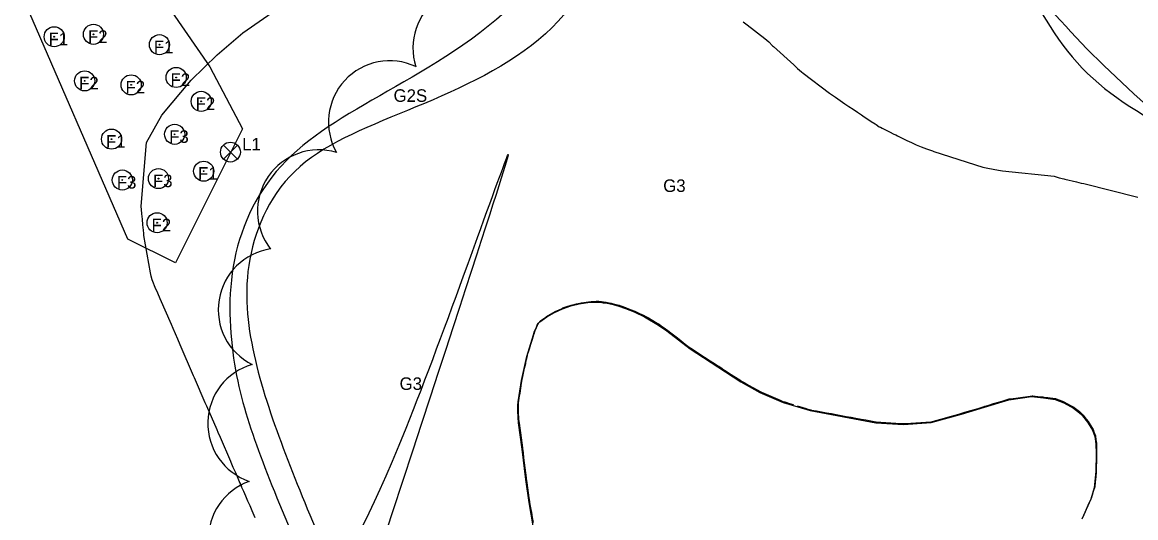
# Model space of a CAD drawing. Extents: x 0 to 512122, y 0 to 6212554.
# Drawn here: x 511390.7 to 511501.5, y 6211379.6 to 6211428.9 of the extents above; entities that cross this region are included whole.
import ezdxf

# ---------------------------------------------------------------- set-up
doc = ezdxf.new("R2010")
doc.units = 0
for name, color, linetype in [('_Låge L1', 7, 'Continuous'), ('_ny fruit trees', 7, 'Continuous'), ('_Paths', 7, 'Continuous'), ('_Spredmingskorridor', 7, 'Continuous'), ('_Spredmingskorridor_hatch', 7, 'Continuous'), ('Bassin - bottom', 7, 'Continuous'), ('Clouds', 7, 'Continuous'), ('MatrikelnummerMaster', 7, 'Continuous'), ('TV_U_AFM_Symbl_Gul', 7, 'Continuous'), ('TV_U_LYS_Nyx330-Trafiksti-x2', 7, 'Continuous')]:
    doc.layers.add(name, color=color, linetype=linetype)

msp = doc.modelspace()

# ---------------------------------------------------------------- linework, layer by layer
at = {"layer": '_Låge L1'}
for p, q in [((511412.11, 6211416.7), (511410.71, 6211415.3)), ((511410.71, 6211416.7), (511412.11, 6211415.3))]:
    msp.add_line(p, q, dxfattribs=at)
msp.add_circle((511411.41, 6211416), 0.989, dxfattribs=at)
at = {"layer": '_ny fruit trees'}
for centre, radius in [((511393.87, 6211427.48), 1), ((511397.78, 6211427.72), 1), ((511393.87, 6211427.48), 0.0426), ((511397.78, 6211427.72), 0.0426), ((511404.34, 6211426.69), 1), ((511404.34, 6211426.69), 0.0426), ((511396.9, 6211423.09), 1), ((511401.53, 6211422.69), 1), ((511406.01, 6211423.43), 1), ((511396.9, 6211423.09), 0.0426), ((511401.53, 6211422.69), 0.0426), ((511406.01, 6211423.43), 0.0426), ((511408.5, 6211421.05), 1), ((511408.5, 6211421.05), 0.0426), ((511399.58, 6211417.29), 1), ((511405.86, 6211417.77), 1), ((511399.58, 6211417.29), 0.0426), ((511405.86, 6211417.77), 0.0426), ((511408.75, 6211414.1), 1), ((511400.65, 6211413.22), 1), ((511404.25, 6211413.36), 1), ((511408.75, 6211414.1), 0.0426), ((511400.65, 6211413.22), 0.0426), ((511404.25, 6211413.36), 0.0426), ((511404.11, 6211408.97), 1), ((511404.11, 6211408.97), 0.0426)]:
    msp.add_circle(centre, radius, dxfattribs=at)
at = {"layer": '_Paths'}
for points in [[(511619.19, 6211386.8), (511596.58, 6211393.48), (511585.39, 6211391.46), (511574.07, 6211393.08), (511564.35, 6211396.52), (511555.15, 6211400.37), (511543.4, 6211408.32), (511538, 6211417.07), (511534.53, 6211422.71), (511527.54, 6211428.6), (511520.9, 6211430.59), (511516.51, 6211433.06), (511513.01, 6211439.69), (511510.47, 6211444.11), (511507.78, 6211450.66), (511503.38, 6211454.99), (511500.2, 6211458.08), (511497.38, 6211464.57)], [(511614.91, 6211385.47), (511596.46, 6211390.92), (511585.44, 6211388.93), (511573.47, 6211390.64), (511563.45, 6211394.19), (511553.96, 6211398.16), (511541.55, 6211406.55), (511535.88, 6211415.76), (511532.61, 6211421.05), (511526.33, 6211426.35), (511519.92, 6211428.28), (511514.64, 6211431.24), (511510.82, 6211438.49), (511508.22, 6211443.01), (511505.66, 6211449.24), (511501.63, 6211453.21), (511498.11, 6211456.63), (511495.08, 6211463.57)], [(511450.04, 6211448.86), (511448.66, 6211442.81), (511441.76, 6211430.61), (511427.39, 6211422.18), (511415.87, 6211415.8), (511410.87, 6211405.41), (511411.54, 6211394.31), (511413.91, 6211386.76), (511418.06, 6211376.54), (511422.94, 6211366.11), (511450.04, 6211448.86), (511422.94, 6211366.11)], [(511452.49, 6211448.38), (511452.1, 6211446.36), (511450.74, 6211439.4), (511444.07, 6211426.76), (511429.55, 6211420.18), (511417.02, 6211415.5), (511412.4, 6211405.18), (511413.42, 6211395.79), (511416.52, 6211386.63), (511420.5, 6211376.91), (511423.94, 6211369.77), (511425.26, 6211367.04)]]:
    msp.add_open_spline(points, degree=3, dxfattribs=at)
at = {"layer": '_Spredmingskorridor'}
for points in [[(511618.63, 6211420.62), (511606.03, 6211410.57), (511596.93, 6211398.18), (511583.32, 6211390.02), (511570.81, 6211390.17), (511555.01, 6211396.48), (511539.8, 6211408.82), (511527.66, 6211423.86), (511513.19, 6211431.42), (511508.4, 6211440.66), (511501.75, 6211451.71), (511492.27, 6211459.06), (511618.63, 6211420.62), (511492.27, 6211459.06)], [(511446.92, 6211452.59), (511459.02, 6211449.61), (511483.05, 6211444.24), (511494.74, 6211426.25), (511518, 6211408.46), (511535.13, 6211387.3), (511545.81, 6211384.87), (511574.75, 6211382.07), (511593.15, 6211386.6), (511609.3, 6211398.19), (511446.92, 6211452.59), (511609.3, 6211398.19)]]:
    msp.add_open_spline(points, degree=3, dxfattribs=at)
at = {"layer": '_Spredmingskorridor_hatch'}
for points in [[(511581.75, 6211389.91), (511577.7, 6211389.37), (511567.86, 6211390.32), (511554, 6211396.47), (511538.61, 6211407.6), (511530.73, 6211425.91), (511512.75, 6211428.39), (511508.4, 6211441.83), (511502.76, 6211452.31), (511495.71, 6211456.96), (511492.31, 6211459.2)], [(511467.29, 6211448.87), (511473.27, 6211448.33), (511486.52, 6211446.7), (511493.23, 6211420.77), (511520.95, 6211413.24), (511528.73, 6211386.92), (511552.28, 6211384.43), (511571.21, 6211380.37), (511589.49, 6211384.41), (511596.58, 6211388.53), (511598.18, 6211389.58)]]:
    msp.add_open_spline(points, degree=3, dxfattribs=at)
at = {"layer": 'Bassin - bottom'}
msp.add_lwpolyline([(511441.56, 6211378.81), (511441.16, 6211381.14), (511440.83, 6211383.42), (511440.46, 6211386.44), (511440.1, 6211389.06), (511440.03, 6211390.23), (511440.03, 6211390.8), (511440.06, 6211391.15), (511440.39, 6211393.28), (511440.92, 6211395.67), (511441.58, 6211397.82), (511441.69, 6211398.18), (511441.83, 6211398.47), (511441.96, 6211398.76), (511442.06, 6211398.93), (511442.11, 6211399), (511442.15, 6211399.05), (511442.2, 6211399.1), (511442.91, 6211399.61), (511443.67, 6211400.05), (511444.46, 6211400.41), (511445.29, 6211400.7), (511446.13, 6211400.91), (511447, 6211401.03), (511447.87, 6211401.08), (511448.03, 6211401.07), (511448.2, 6211401.05), (511448.5, 6211401.01), (511448.9, 6211400.95), (511449.37, 6211400.85), (511450.07, 6211400.68), (511450.75, 6211400.42), (511451.6, 6211400.09), (511452.63, 6211399.6), (511454.03, 6211398.79), (511454.85, 6211398.2), (511457.19, 6211396.41), (511459.94, 6211394.62), (511462.23, 6211393.14), (511464.1, 6211392.09), (511466.42, 6211391.09), (511469.12, 6211390.27), (511475.64, 6211389.07), (511478.42, 6211388.9), (511481.15, 6211389.1), (511484.18, 6211389.93), (511486.47, 6211390.63), (511488.88, 6211391.36), (511491.16, 6211391.66), (511492.33, 6211391.55), (511493.49, 6211391.39), (511494.38, 6211391.04), (511495.32, 6211390.52), (511496.09, 6211389.92), (511496.73, 6211389.11), (511497.23, 6211388.32), (511497.47, 6211387.69), (511497.57, 6211386.98), (511497.58, 6211385.96), (511497.54, 6211384.21), (511497.4, 6211382.59), (511497.04, 6211381.47), (511496.15, 6211379.46)], dxfattribs=at)
at = {"layer": 'Clouds'}
for centre, start, end in [((511435.68, 6211426.38), 52.9408, 197.9408), ((511427.27, 6211418.99), 64.7309, 209.7309), ((511420.21, 6211410.12), 73.1767, 218.1767), ((511416.3, 6211400.32), 98.3357, 243.3357), ((511415.26, 6211389), 106.1484, 251.1484), ((511415.32, 6211377.48), 109.4778, 254.4778)]:
    msp.add_arc(centre, 6.1, start, end, dxfattribs=at)
at = {"layer": 'MatrikelnummerMaster'}
msp.add_lwpolyline([(511390.69, 6211431.59), (511399.26, 6211439.11), (511409.35, 6211424.49), (511412.6, 6211418.32), (511405.93, 6211404.98), (511401.2, 6211407.34), (511390.69, 6211431.59), (511390.69, 6211431.59), (511390.69, 6211431.59), (511390.69, 6211431.59), (511390.69, 6211431.59)], dxfattribs=at)
at = {"layer": 'TV_U_LYS_Nyx330-Trafiksti-x2'}
for points in [[(511413.88, 6211379.6), (511413.57, 6211380.31), (511413.36, 6211380.79), (511413.16, 6211381.26), (511412.95, 6211381.74), (511412.74, 6211382.22), (511412.53, 6211382.7), (511412.35, 6211383.13), (511412.53, 6211382.71), (511412.32, 6211383.19), (511412.12, 6211383.67), (511411.91, 6211384.14), (511411.7, 6211384.62), (511411.5, 6211385.1), (511411.45, 6211385.19), (511410.41, 6211387.61), (511410.2, 6211388.09), (511410.08, 6211388.36), (511409.06, 6211390.72), (511408.91, 6211391.06), (511407.83, 6211393.54), (511407.75, 6211393.74), (511406.41, 6211396.82), (511406.17, 6211397.37), (511405.94, 6211397.91), (511405.7, 6211398.45), (511405.54, 6211398.83), (511404.42, 6211401.41), (511404.18, 6211401.97), (511403.93, 6211402.54), (511403.69, 6211403.11), (511403.61, 6211403.28), (511403.52, 6211403.65), (511403.45, 6211403.97), (511402.79, 6211407.7), (511402.78, 6211407.89), (511402.75, 6211408.24), (511402.7, 6211408.77), (511402.65, 6211409.31), (511402.6, 6211409.85), (511402.6, 6211409.9), (511402.53, 6211410.63), (511403.06, 6211416.95), (511404.59, 6211419.67), (511407.5, 6211423.15), (511410.09, 6211425.68), (511412.65, 6211427.86), (511418.83, 6211432.18)], [(511462.45, 6211428.96), (511462.84, 6211428.68), (511464.61, 6211427.32), (511465, 6211426.96), (511465.37, 6211426.59), (511465.46, 6211426.51), (511467.49, 6211424.67), (511467.87, 6211424.33), (511468.25, 6211423.99), (511468.43, 6211423.84), (511471.03, 6211421.87), (511471.44, 6211421.59), (511471.64, 6211421.45), (511472.57, 6211420.81), (511472.98, 6211420.54), (511473.4, 6211420.26), (511473.82, 6211419.98), (511474.23, 6211419.7), (511474.5, 6211419.52), (511474.77, 6211419.34), (511475.19, 6211419.06), (511475.58, 6211418.8), (511475.68, 6211418.73), (511475.99, 6211418.53), (511476.11, 6211418.47), (511476.27, 6211418.39), (511476.56, 6211418.25), (511477.01, 6211418.02), (511477.46, 6211417.8), (511477.64, 6211417.71), (511477.82, 6211417.63), (511478.29, 6211417.4), (511478.75, 6211417.17), (511479.22, 6211416.94), (511479.68, 6211416.71), (511480.16, 6211416.51), (511480.7, 6211416.32), (511481.29, 6211416.11), (511481.43, 6211416.05), (511486.3, 6211414.51), (511486.82, 6211414.4), (511487.34, 6211414.29), (511487.86, 6211414.2), (511488.28, 6211414.15), (511493.4, 6211413.6), (511493.89, 6211413.45), (511494.38, 6211413.33), (511494.47, 6211413.31), (511495.62, 6211413.03), (511496.11, 6211412.92), (511496.37, 6211412.86), (511501.73, 6211411.53)], [(511441.57, 6211379.14), (511441.48, 6211379.63), (511441.4, 6211380.12), (511441.31, 6211380.61), (511441.23, 6211381.11), (511441.21, 6211381.21), (511441.15, 6211381.6), (511441.08, 6211382.1), (511441.01, 6211382.59), (511440.94, 6211383.09), (511440.88, 6211383.5), (511440.87, 6211383.58), (511440.81, 6211384.08), (511440.75, 6211384.57), (511440.69, 6211385.07), (511440.63, 6211385.57), (511440.57, 6211386.06), (511440.52, 6211386.51), (511440.51, 6211386.56), (511440.44, 6211387.05), (511440.37, 6211387.55), (511440.31, 6211388.05), (511440.24, 6211388.54), (511440.17, 6211389.04), (511440.16, 6211389.13), (511440.13, 6211389.53), (511440.1, 6211390.03), (511440.08, 6211390.3), (511440.08, 6211390.53), (511440.08, 6211390.88), (511440.1, 6211391.03), (511440.11, 6211391.23), (511440.16, 6211391.53), (511440.24, 6211392.02), (511440.31, 6211392.52), (511440.39, 6211393.01), (511440.44, 6211393.36), (511440.48, 6211393.5), (511440.58, 6211393.99), (511440.69, 6211394.48), (511440.8, 6211394.97), (511440.83, 6211395.12), (511440.9, 6211395.46), (511440.97, 6211395.74), (511441.03, 6211395.94), (511441.08, 6211396.11), (511441.18, 6211396.42), (511441.32, 6211396.9), (511441.47, 6211397.37), (511441.62, 6211397.85), (511441.63, 6211397.9), (511441.74, 6211398.25), (511441.78, 6211398.32), (511441.88, 6211398.54), (511441.99, 6211398.78), (511442.02, 6211398.83), (511442.11, 6211399.01), (511442.16, 6211399.08), (511442.2, 6211399.13), (511442.25, 6211399.18), (511442.27, 6211399.19), (511442.61, 6211399.43), (511442.67, 6211399.48), (511442.96, 6211399.69), (511443.09, 6211399.76), (511443.52, 6211400.01), (511443.72, 6211400.12), (511443.97, 6211400.23), (511444.12, 6211400.3), (511444.42, 6211400.44), (511444.51, 6211400.49), (511444.89, 6211400.62), (511445.34, 6211400.77), (511445.36, 6211400.78), (511445.85, 6211400.9), (511446.19, 6211400.98), (511446.33, 6211401), (511446.83, 6211401.08), (511447.05, 6211401.11), (511447.33, 6211401.13), (511447.83, 6211401.15), (511447.92, 6211401.16), (511448.08, 6211401.15), (511448.25, 6211401.13), (511448.32, 6211401.12), (511448.39, 6211401.11), (511448.39, 6211401.11), (511448.56, 6211401.09), (511448.74, 6211401.06), (511448.82, 6211401.05), (511448.95, 6211401.03), (511449.31, 6211400.95), (511449.42, 6211400.93), (511449.8, 6211400.84), (511450.12, 6211400.76), (511450.28, 6211400.7), (511450.74, 6211400.52), (511450.81, 6211400.5), (511451.21, 6211400.34), (511451.65, 6211400.17), (511451.67, 6211400.16), (511452.13, 6211399.94), (511452.58, 6211399.73), (511452.68, 6211399.68), (511453.01, 6211399.49), (511453.45, 6211399.24), (511453.88, 6211398.99), (511454.08, 6211398.87), (511454.3, 6211398.72), (511454.71, 6211398.42), (511454.91, 6211398.28), (511455.11, 6211398.12), (511455.5, 6211397.82), (511455.9, 6211397.51), (511456.29, 6211397.21), (511456.69, 6211396.9), (511457.09, 6211396.6), (511457.24, 6211396.48), (511457.5, 6211396.31), (511457.92, 6211396.04), (511458.34, 6211395.77), (511458.76, 6211395.5), (511459.18, 6211395.23), (511459.6, 6211394.96), (511460, 6211394.7), (511460.02, 6211394.69), (511460.32, 6211394.49), (511460.44, 6211394.41), (511460.59, 6211394.31), (511460.86, 6211394.14), (511461.27, 6211393.87), (511461.69, 6211393.59), (511462.11, 6211393.32), (511462.28, 6211393.21), (511462.54, 6211393.07), (511462.98, 6211392.82), (511463.41, 6211392.58), (511463.85, 6211392.33), (511464.15, 6211392.16), (511464.29, 6211392.1), (511464.75, 6211391.9), (511465.21, 6211391.71), (511465.67, 6211391.51), (511466.13, 6211391.31), (511466.47, 6211391.16), (511466.59, 6211391.13), (511467.07, 6211390.98), (511467.43, 6211390.87), (511467.47, 6211390.86)], [(511467.82, 6211390.75), (511468.3, 6211390.61), (511468.71, 6211390.48), (511468.78, 6211390.46), (511469.17, 6211390.34), (511469.26, 6211390.33), (511469.75, 6211390.24), (511470.24, 6211390.15), (511470.73, 6211390.06), (511471.23, 6211389.97), (511471.72, 6211389.88), (511472.21, 6211389.79), (511472.7, 6211389.7), (511473.19, 6211389.61), (511473.68, 6211389.52), (511474.18, 6211389.43), (511474.67, 6211389.34), (511475.16, 6211389.25), (511475.65, 6211389.16), (511475.69, 6211389.15), (511476.15, 6211389.12), (511476.65, 6211389.09), (511477.15, 6211389.06), (511477.65, 6211389.03), (511478.15, 6211389), (511478.48, 6211388.98), (511478.65, 6211388.99), (511479.14, 6211389.03), (511479.64, 6211389.06), (511480.14, 6211389.1), (511480.64, 6211389.13), (511481.14, 6211389.17), (511481.21, 6211389.17), (511481.62, 6211389.29), (511482.11, 6211389.42), (511482.59, 6211389.55), (511483.07, 6211389.69), (511483.55, 6211389.82), (511484.03, 6211389.96), (511484.23, 6211390.01), (511484.51, 6211390.1), (511484.99, 6211390.24), (511485.47, 6211390.39), (511485.95, 6211390.53), (511486.43, 6211390.68), (511486.52, 6211390.7), (511486.9, 6211390.82), (511487.38, 6211390.97), (511487.86, 6211391.11), (511488.34, 6211391.26), (511488.82, 6211391.4), (511488.93, 6211391.44), (511489.31, 6211391.49), (511489.81, 6211391.55), (511490.3, 6211391.62), (511490.8, 6211391.68), (511491.21, 6211391.74), (511491.29, 6211391.73), (511491.79, 6211391.68), (511492.29, 6211391.63), (511492.38, 6211391.62), (511492.78, 6211391.57), (511493.28, 6211391.5), (511493.54, 6211391.47), (511493.76, 6211391.38), (511494.23, 6211391.2), (511494.43, 6211391.12), (511494.68, 6211390.98), (511495.11, 6211390.74), (511495.38, 6211390.6), (511495.53, 6211390.47), (511495.93, 6211390.17), (511496.14, 6211390), (511496.28, 6211389.82), (511496.59, 6211389.43), (511496.61, 6211389.4), (511496.78, 6211389.18), (511496.89, 6211389.02), (511497.15, 6211388.6), (511497.28, 6211388.4), (511497.37, 6211388.15), (511497.52, 6211387.76), (511497.53, 6211387.68), (511497.6, 6211387.18), (511497.62, 6211387.06), (511497.62, 6211386.69), (511497.62, 6211386.67), (511497.62, 6211386.67), (511497.62, 6211386.67), (511497.62, 6211386.57), (511497.63, 6211386.48), (511497.63, 6211386.43), (511497.63, 6211386.42), (511497.63, 6211386.19), (511497.63, 6211386.15), (511497.63, 6211386.03), (511497.62, 6211385.69), (511497.61, 6211385.19), (511497.6, 6211384.69), (511497.59, 6211384.29), (511497.58, 6211384.19), (511497.54, 6211383.69), (511497.49, 6211383.19), (511497.45, 6211382.69), (511497.45, 6211382.67), (511497.3, 6211382.22), (511497.18, 6211381.84), (511497.15, 6211381.74), (511497.09, 6211381.54), (511496.97, 6211381.27), (511496.77, 6211380.82), (511496.56, 6211380.36), (511496.5, 6211380.21), (511496.38, 6211379.95), (511496.36, 6211379.9), (511496.2, 6211379.54)]]:
    msp.add_lwpolyline(points, dxfattribs=at)

# ---------------------------------------------------------------- texts
at = {"layer": 'TV_U_AFM_Symbl_Gul'}
for s, p in [('F2', (511397.23, 6211426.87)), ('F1', (511393.31, 6211426.63)), ('F1', (511403.79, 6211425.84)), ('F2', (511405.45, 6211422.58)), ('F2', (511396.35, 6211422.24)), ('F2', (511400.97, 6211421.84)), ('F2', (511407.95, 6211420.2)), ('G2S', (511427.65, 6211421)), ('F3', (511405.31, 6211416.92)), ('F1', (511399.03, 6211416.44)), ('L1', (511412.58, 6211416.16)), ('F3', (511400.1, 6211412.37)), ('F3', (511403.7, 6211412.51)), ('F1', (511408.19, 6211413.25)), ('G3', (511454.49, 6211412.03)), ('F2', (511403.56, 6211408.12)), ('G3', (511428.25, 6211392.33))]:
    msp.add_text(s, height=1.25, dxfattribs=at).set_placement(p)

doc.saveas('drawing.dxf')
